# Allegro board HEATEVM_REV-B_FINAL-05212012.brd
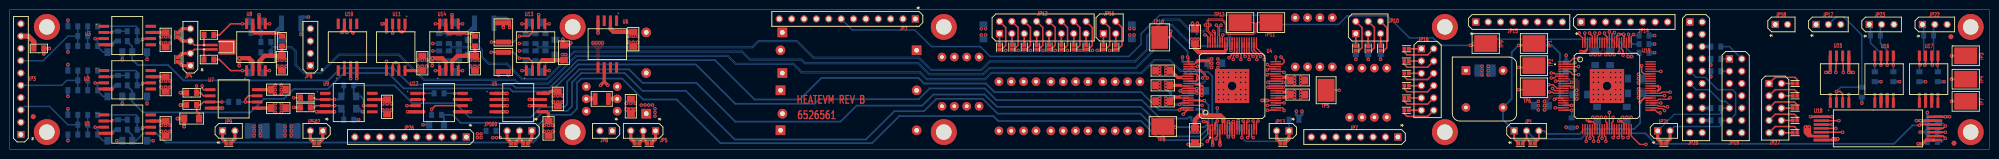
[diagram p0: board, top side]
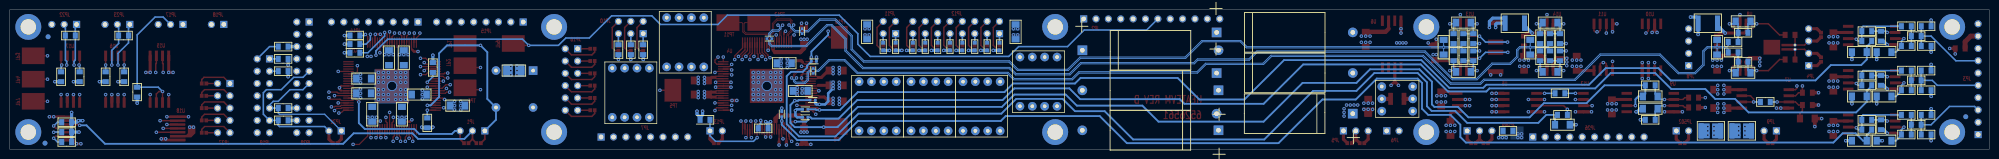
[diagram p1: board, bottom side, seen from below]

Outline 406.4 x 28.83 mm; copper layers: TOP, L2_GND, L3_PWR, L4_SIG, L5_SIG, L6_PWR, L7_GND, BOTTOM. Coordinates in mm from the lower left corner of the outline.
Outline path: 0,28.83 0,0 406.4,0 406.4,28.83 0,28.83

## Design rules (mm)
net group DP1: nets ADC_CH5M ADC_CH5P
net group DP2: nets ADC_CH7M ADC_CH7P
net group DP3: nets ADC_CH8M ADC_CH8P

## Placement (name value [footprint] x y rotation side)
C1  0.1u  [1206]  127.51 8.89 90 top
C2  68u 60V 200C  [CAP_AXL_641X312_1100]  158.62 24.13 180 bottom
C3  68u 60V 200C  [CAP_AXL_641X312_1100]  158.24 12.19 0 bottom
C4  68u 60V 200C  [CAP_AXL_641X312_1100]  158.62 15.75 180 bottom
C5  1u-DNI  [1210]  121.54 10.41 0 top
C7  68u 60V 200C  [CAP_AXL_641X312_1100]  186.18 20.45 180 bottom
C8  0.1u  [1206]  244.09 12.06 180 bottom
C9  0.1u  [1206]  112.52 10.41 270 top
C10  0.1u  [1206]  236.73 13.21 180 top
C11  10n  [1206]  90.17 16 0 bottom
C12  0.1u  [1206]  243.33 2.92 270 top
C13  0.1u  [1206]  243.33 23.24 90 top
C14  0.1u  [1206]  230.38 24.26 90 bottom
C15  68u 60V 200C  [CAP_AXL_641X312_1100]  158.24 3.94 0 bottom
C16  0.1u  [1206]  236.73 16.26 180 top
C17  0.033u  [0805]  17.02 7.11 0 bottom
C18  0.1u  [1206]  50.55 15.81 0 bottom
C20  0.1u  [1206]  50.55 26.42 0 bottom
C21  0.1u  [1206]  128.02 22.73 270 top
C22  0.1u  [1206]  37.34 6.35 180 top
C23  0.1u  [1206]  26.67 20.07 0 bottom
C24  0.033u  [0805]  17.02 16.26 0 bottom
C25  0.1u  [1206]  26.67 10.92 0 bottom
C26  0.1u  [1206]  32 22.61 270 top
C27  1u  [CAP_THVT_SMX3_300X250_100]  118.36 12.95 0 bottom
C28  0.1u  [1206]  325.88 7.24 90 bottom
C29  0.1u  [1206]  322.33 11.3 0 bottom
C30  0.1u  [1206]  21.59 20.07 0 bottom
C31  0.1u  [1206]  328.55 18.92 270 bottom
C32  0.033u  [0805]  17.02 25.4 0 bottom
C33  0.1u  [1206]  21.59 10.92 0 bottom
C34  0.1u  [1206]  236.73 9.91 180 top
C35  0.1u  [1206]  32 13.46 270 top
C37  0.1u  [1206]  21.59 1.78 0 bottom
C39  0.1u  [1206]  32 4.32 270 top
C40  0.1u  [1206]  26.67 1.78 0 bottom
C42  68u 60V 200C  [CAP_AXL_641X312_1100]  130.68 7.37 0 bottom
C43  0.1u  [1206]  264.41 14.22 0 top
C44  0.1u  [1206]  110.62 4.32 270 top
C45  10n  [1206]  69.6 10.92 0 bottom
C48  10n  [1206]  90.17 26.16 0 bottom
C50  0.1u  [1206]  69.6 8.38 0 bottom
C51  0.1u  [1206]  325.5 18.92 270 bottom
C52  0.1u  [1206]  314.45 9.02 180 bottom
C53  0.1u  [1206]  331.98 7.24 90 bottom
C54  0.1u  [1206]  87.63 5.08 180 bottom
C56  10n  [1206]  107.95 26.16 0 bottom
C57  10n  [1206]  112.01 21.08 270 bottom
C58  10n  [1206]  107.95 16 0 bottom
C62  SMX4-10u  [CAP_THVT_SMX4_440X400_100]  221.36 13.97 270 bottom
C500  0.1u  [1206]  55.12 12.32 0 top
C501  0.1u  [1206]  55.12 8.51 0 top
C502  0.1u  [1206]  55.88 17.78 270 top
C503  0.22u  [1812]  50.8 3.81 0 bottom
C504  10n  [1206]  55.88 21.08 270 bottom
C505  0.22u  [1812]  57.78 26.04 0 bottom
C506  0.22u  [1812]  101.35 18.03 270 top
C507  0.22u  [1812]  101.35 24.13 90 top
C508  0.1u  [1206]  113.79 19.94 90 top
C509  0.1u  [1206]  95.5 17.78 270 top
C510  0.1u  [1206]  77.47 8.76 270 top
C511  10n  [1206]  94.23 21.08 270 bottom
C512  0.1u  [1206]  84.71 17.78 90 top
C513  0.22u  [1812]  57.15 3.81 180 bottom
C514  0.1u  [1206]  264.41 11.3 0 top
C517  0.22u  [1812]  97.41 26.04 0 bottom
C518  0.1u  [1206]  247.4 17.78 0 bottom
C519  1n  [0402]  241.43 16.19 90 bottom
C520  1n  [0402]  243.71 24.38 90 bottom
C521  1n  [0402]  250.44 22.86 180 bottom
C522  100p  [0402]  247.9 7.24 90 bottom
C523  100p  [0402]  243.08 6.6 0 bottom
C524  100p  [0402]  243.08 8.26 0 bottom
C525  100p  [0402]  241.3 18.16 180 bottom
C526  100p  [0402]  241.55 10.16 180 bottom
C527  SMX4-10u  [CAP_THVT_SMX4_440X400_100]  199.01 19.05 270 bottom
C528  SMX4-10u  [CAP_THVT_SMX4_440X400_100]  210.69 13.97 270 bottom
C530  SMX4-10u  [CAP_THVT_SMX4_440X400_100]  232.03 13.97 270 bottom
C531  SMX4-10u  [CAP_THVT_SMX4_440X400_100]  263.91 17.02 90 bottom
C532  SMX4-10u  [CAP_THVT_SMX4_440X400_100]  275.08 6.6 90 bottom
C533  0.1u  [1206]  199.9 24.26 90 bottom
C534  0.1u  [1206]  302.89 16.26 180 bottom
C535  0.1u  [1206]  333.76 11.56 180 bottom
C536  0.1u  [1206]  333.76 14.61 180 bottom
JP1  FLASH_CLK  [HDR_THVT_1X3_100]  308.86 3.81 90 top
JP2  PWR_INPUT  [HDR_THVT_1X12_100]  185.93 26.92 270 top
JP3  AMP_INPUT_A  [HDR_THVT_1X10_100]  2.29 3.05 180 top
JP4  EXT_RTD  [HDR_THVT_1X4_100]  37.08 17.27 180 top
JP5  VREF_SEL  [HDR_THVT_1X3_100]  132.59 3.81 270 top
JP6  EXT_VREF  [HDR_THVT_1X2_100]  123.7 3.81 270 top
JP7  DOUT_TAP  [HDR_THVT_1X8_100]  284.99 2.54 270 top
JP8  CONN PCB 4  [HDR_THVT_1X4_100]  61.72 17.27 180 top
JP9  AMP5_VCOM_SEL  [HDR_THVT_1X2_100]  43.69 3.81 90 top
JP10  AD_FORMAT  [HDR_THVT_2X3_100_M]  276.35 23.88 90 top
JP11  AD_MODE  [HDR_THVT_2X2_100_M]  224.54 23.88 90 top
JP12  DISABLE_CHANNEL  [HDR_THVT_2X8_100_M]  203.2 23.88 90 top
JP13  DISABLE_CLKDIV  [HDR_THVT_1X2_100]  262.64 3.81 270 top
JP14  GPIO  [HDR_THVT_1X8_100]  322.58 26.29 90 top
JP15  HET_AND_GPIO  [HDR_THVT_1X8_100]  300.99 26.29 90 top
JP16  AD_CONTROL  [HDR_THVT_2X6_100_M]  289.81 20.76 0 top
JP17  RS485_CTRL  [HDR_THVT_1X3_100]  370.84 25.78 90 top
JP18  RS485_DATA  [HDR_THVT_1X2_100]  362.46 25.78 90 top
JP19  JTAG_7X2  [HDR_THVT_2X7_100_M]  353.06 18.67 0 top
JP20  JTAG_10X2  [HDR_THVT_2X10_100_M]  344.93 26.29 0 top
JP21  JTCLK_SEL  [HDR_THVT_1X2_100]  338.33 3.81 90 top
JP22  CAN1  [HDR_THVT_1X3_100]  392.68 25.78 90 top
JP23  CAN2  [HDR_THVT_1X3_100]  381.76 25.78 90 top
JP26  AMP_INPUTS_B  [HDR_THVT_1X10_100]  93.73 2.54 270 top
JP27  SPI2_M-IF_CNTRL  [HDR_THVT_2X5_100_M]  361.19 13.59 0 top
JP500  VCOM_SEL  [HDR_THVT_1X3_100]  107.19 3.81 270 top
JP502  AMP8_VCOM_SEL  [HDR_THVT_1X2_100]  64.26 3.81 270 top
MNT1  440_SCREW_MOUNT  [MFG_125_PTH]  7.62 3.56 0 top
MNT2  440_SCREW_MOUNT  [MFG_125_PTH]  7.62 25.27 0 top
MNT3  440_SCREW_MOUNT  [MFG_125_PTH]  115.57 3.56 0 top
MNT4  440_SCREW_MOUNT  [MFG_125_PTH]  115.57 25.27 0 top
MNT5  440_SCREW_MOUNT  [MFG_125_PTH]  294.64 3.56 0 top
MNT6  440_SCREW_MOUNT  [MFG_125_PTH]  294.64 25.27 0 top
MNT7  440_SCREW_MOUNT  [MFG_125_PTH]  402.59 3.56 0 top
MNT8  440_SCREW_MOUNT  [MFG_125_PTH]  402.59 25.27 0 top
MNT9  440_SCREW_MOUNT  [MFG_125_PTH]  191.77 25.27 0 top
MNT10  440_SCREW_MOUNT  [MFG_125_PTH]  191.77 3.56 0 top
NOREF  -  []  0 0 0 top
NOREF#2  -  []  0 0 90 top
NOREF#3  -  [unnamed#2]  4.83 6.73 0 top
NOREF#4  -  [unnamed#2]  399.16 1.27 0 top
NOREF#5  -  []  371.98 107.95 0 top
NOREF#6  -  [unnamed#2]  398.53 23.24 0 top
NOREF#7  -  []  146.56 13.46 0 top
NOREF#8  -  []  375.67 17.4 180 bottom
NOREF#9  -  [unnamed#2]  398.53 23.24 180 bottom
NOREF#10  -  [unnamed#2]  399.16 1.27 180 bottom
NOREF#11  -  [unnamed#2]  4.83 6.73 180 bottom
OSC1  FMI_7M500_OSC  [XTAL_4_THVT_505X505]  302.77 12.45 270 top
R1  10K  [0603]  205.74 21.21 90 bottom
R2  10K  [0603]  224.54 21.21 90 bottom
R3  10K  [0805]  281.43 20.57 90 bottom
R4  10K  [0805]  278.89 20.57 90 bottom
R5  10K  [0805]  276.35 20.57 90 bottom
R6  1.0K  [0805]  251.71 4.32 180 bottom
R7  10K  [0603]  227.08 21.21 90 bottom
R8  10K  [0603]  203.2 21.21 90 bottom
R9  10K  [0603]  208.28 21.21 90 bottom
R10  10K  [0603]  210.82 21.21 90 bottom
R11  10K  [0603]  213.36 21.21 90 bottom
R12  10K  [0603]  215.9 21.21 90 bottom
R13  80.6K  [0805]  14.99 5.08 0 bottom
R14  2.00K  [0805]  5.97 20.83 0 top
R15  49.9  [0805]  25.15 4.06 180 bottom
R16  20K-DNI  [0805]  12.95 7.11 180 bottom
R17  2.0K-DNI  [0805]  12.95 3.05 0 bottom
R18  22K  [0805]  40.89 23.62 180 top
R19  68K  [0805]  50.55 24.07 180 bottom
R20  68K  [0805]  50.55 18.1 180 bottom
R21  22K  [0805]  40.89 18.54 180 top
R24  1.0K  [0805]  37.34 11.68 0 top
R25  1.0K  [0805]  45.97 9.78 0 bottom
R26  220  [0805]  37.34 9.14 0 top
R27  20K-DNI  [0805]  12.95 16.26 180 bottom
R28  2.00K-DNI  [0805]  12.95 12.19 0 bottom
R29  80.6K  [0805]  14.99 14.22 0 bottom
R30  10K  [0805]  17.02 3.05 0 bottom
R31  49.9  [0805]  25.15 13.21 180 bottom
R32  20K-DNI  [0805]  12.95 25.4 180 bottom
R33  2.00K-DNI  [0805]  12.95 21.34 0 bottom
R34  80.6K  [0805]  14.99 23.37 0 bottom
R35  49.9  [0805]  25.15 22.35 180 bottom
R37  10K  [0805]  60.71 10.67 180 top
R38  10K  [0805]  69.6 13.21 0 bottom
R39  10K  [0805]  60.71 8.64 0 top
R40  10K  [0805]  69.6 6.1 0 bottom
R42  402  [0805]  88.14 11.56 0 bottom
R44  10K  [0805]  17.02 12.19 0 bottom
R45  200  [0805]  87.63 7.11 0 bottom
R46  10K  [0805]  17.02 21.34 0 bottom
R47  10K  [0805]  107.95 22.86 90 bottom
R48  10K  [0805]  105.92 22.86 270 bottom
R49  49.9  [0805]  109.98 22.86 90 bottom
R50  49.9  [0805]  109.98 19.3 270 bottom
R51  10K  [0805]  107.95 19.3 270 bottom
R52  10K  [0805]  105.92 19.3 90 bottom
R53  200  [0805]  88.14 22.86 270 bottom
R54  50K  [0805]  90.17 22.86 90 bottom
R55  200  [0805]  88.14 19.3 270 bottom
R56  50K  [0805]  90.17 19.3 270 bottom
R57  200  [0805]  92.2 22.86 90 bottom
R58  200  [0805]  92.2 19.3 270 bottom
R59  200  [0805]  98.81 3.81 0 bottom
R60  10K  [0603]  218.44 21.21 90 bottom
R61  10K  [0603]  220.98 21.21 90 bottom
R62  10K  [0805]  263.65 6.1 0 bottom
R63  10K  [0805]  392.05 14.99 90 bottom
R64  10K  [0805]  380.24 11.81 270 bottom
R65  10K  [0805]  350.27 5.97 0 bottom
R66  10K  [0805]  350.27 8.51 0 bottom
R67  10K  [0805]  350.27 18.67 180 bottom
R68  10K-DNI  [0805]  350.27 16.13 180 bottom
R69  10K  [0805]  350.27 21.21 0 bottom
R70  33K  [0805]  335.53 19.94 180 bottom
R71  33K  [0805]  319.53 16.89 90 bottom
R72  10K  [0805]  395.86 14.99 90 bottom
R73  10K  [0805]  382.9 14.99 90 bottom
R74  10K  [0805]  386.71 14.99 90 bottom
R78  120  [0805]  383.03 23.5 180 bottom
R79  120  [0805]  393.95 23.5 180 bottom
R81  33K  [0805]  394.72 3.56 180 bottom
R83  33K  [0805]  335.53 21.72 180 bottom
R84  33K  [0805]  335.53 23.5 180 bottom
R85  33K  [0805]  320.68 5.46 90 bottom
R92  10K  [0805]  25.15 6.1 0 bottom
R93  10K-DNI  [0805]  22.23 5.08 90 bottom
R94  10K  [0805]  25.15 15.24 0 bottom
R95  10K-DNI  [0805]  22.23 14.22 90 bottom
R96  10K-DNI  [0805]  22.23 23.37 90 bottom
R97  10K  [0805]  25.15 24.38 0 bottom
R98  33K  [0805]  394.72 5.59 180 bottom
R99  33K  [0805]  394.72 1.52 180 bottom
R500  10K  [0805]  55.88 22.35 90 top
R501  49.9  [0805]  52.58 20 180 bottom
R502  49.9  [0805]  52.58 22.16 180 bottom
R503  10K-DNI  [0805]  95.5 22.35 90 top
RTD  1.0K  [SENSOR_RTD_118X79_35]  43.69 21.08 180 top
SB1  SBridge  [SHORTING_BRIDGE]  34.54 23.62 90 top
SB2  SBridge  [SHORTING_BRIDGE]  34.54 18.54 270 top
SB3  SBridge  [SHORTING_BRIDGE]  131.32 1.27 0 top
SB4  SBridge  [SHORTING_BRIDGE]  128.78 1.27 180 top
SB5  SBridge  [SHORTING_BRIDGE]  44.96 1.27 180 top
SB6  SBridge  [SHORTING_BRIDGE]  62.99 1.27 0 top
SB7  SBridge  [SHORTING_BRIDGE]  105.92 1.27 180 top
SB8  SBridge  [SHORTING_BRIDGE]  103.38 1.27 0 top
SB9  SBridge  [SHORTING_BRIDGE]  203.2 21.08 90 top
SB10  SBridge  [SHORTING_BRIDGE]  205.74 21.08 90 top
SB11  SBridge  [SHORTING_BRIDGE]  208.28 21.08 90 top
SB12  SBridge  [SHORTING_BRIDGE]  210.82 21.08 90 top
SB13  SBridge  [SHORTING_BRIDGE]  213.36 21.08 90 top
SB14  SBridge  [SHORTING_BRIDGE]  215.9 21.08 90 top
SB15  SBridge  [SHORTING_BRIDGE]  218.44 21.08 90 top
SB16  SBridge  [SHORTING_BRIDGE]  220.98 21.08 90 top
SB17  SBridge  [SHORTING_BRIDGE]  276.35 20.83 90 top
SB18  SBridge  [SHORTING_BRIDGE]  278.89 20.83 90 top
SB19  SBridge  [SHORTING_BRIDGE]  281.43 20.83 90 top
SB20  SBridge  [SHORTING_BRIDGE]  224.54 21.08 90 top
SB21  SBridge  [SHORTING_BRIDGE]  261.37 1.27 0 top
SB22  SBridge  [SHORTING_BRIDGE]  227.08 21.08 90 top
SB23  SBridge  [SHORTING_BRIDGE]  312.67 1.27 0 top
SB24  SBridge  [SHORTING_BRIDGE]  310.13 1.27 180 top
SB25  SBridge  [SHORTING_BRIDGE]  339.6 1.27 180 top
SB26  SBridge  [SHORTING_BRIDGE]  366.52 13.59 180 top
SB27  SBridge  [SHORTING_BRIDGE]  366.52 11.05 180 top
SB28  SBridge  [SHORTING_BRIDGE]  366.52 8.51 180 top
SB29  SBridge  [SHORTING_BRIDGE]  366.52 5.97 180 top
SB30  SBridge  [SHORTING_BRIDGE]  366.52 3.43 180 top
SB31  SBridge  [SHORTING_BRIDGE]  286.77 15.68 0 top
SB32  SBridge  [SHORTING_BRIDGE]  286.77 18.22 0 top
SB33  SBridge  [SHORTING_BRIDGE]  286.77 20.76 0 top
SB34  SBridge  [SHORTING_BRIDGE]  286.77 13.14 0 top
SB35  SBridge  [SHORTING_BRIDGE]  286.77 10.6 0 top
SB36  SBridge  [SHORTING_BRIDGE]  286.77 8.06 0 top
TP1  MCU_RSTn  [TP_SMVT_112X150]  312.93 21.84 90 top
TP2  MCU_AWD  [TP_SMVT_112X150]  312.93 17.27 90 top
TP3  CAN1_LPBK  [TP_SMVT_112X150]  401.57 19.3 90 top
TP4  CAN2_LPBK  [TP_SMVT_112X150]  401.57 14.48 90 top
TP5  ADC_TEST  [TP_SMVT_112X150]  270.26 12.19 0 top
TP6  SCI1TX  [TP_SMVT_112X150]  312.93 12.7 270 top
TP7  FLSH_WPn  [TP_SMVT_112X150]  401.57 9.91 90 top
TP8  ADC_CH4  [TP_SMVT_112X150]  236.73 4.7 90 top
TP9  PORSTn  [TP_SMVT_112X150]  303.02 21.84 90 top
TP10  ADC_CH6  [TP_SMVT_112X150]  236.09 23.11 180 top
TP11  ADC_CH7p  [TP_SMVT_112X150]  258.95 26.16 270 top
TP12  ADC_CH7m  [TP_SMVT_112X150]  252.6 26.16 270 top
U1  OPA211SHKJ  [CDFF_8_289X232_50]  24.13 5.21 0 top
U2  OPA211SHKJ  [CDFF_8_289X232_50]  24.13 14.35 0 top
U3  OPA211SHKJ  [CDFF_8_289X232_50]  24.13 23.5 0 top
U4  ADS1278SHFQ  [CQFP_84_544X544_20]  250.95 13.08 90 top
U5  OPA2333SHKJ  [CDFF_8_289X232_50]  104.39 9.65 0 top
U6  REF5025SHKJ  [CDFF_8_289X232_50]  122.68 21.72 270 top
U7  OPA2333SHKJ  [CDFF_8_289X232_50]  45.97 10.41 0 top
U8  THS4521SHKJ  [CDFF_8_289X232_50]  50.55 21.08 90 top
U9  OPA211SHKJ  [CDFF_8_289X232_50]  69.6 9.65 0 top
U10  OPA211SHKJ  [CDFF_8_289X232_50]  69.34 21.08 90 top
U11  OPA2333SHKJ  [CDFF_8_289X232_50]  79.25 21.08 270 top
U12  INA333SHKJ  [CDFF_8_289X232_50]  88.14 9.65 0 top
U13  THS4521SHKJ  [CDFF_8_289X232_50]  107.95 21.08 90 top
U14  THS4521SHKJ  [CDFF_8_289X232_50]  90.17 21.08 90 top
U15  SN65HVD11SHKJ  [CDFF_8_289X232_50]  375.67 14.48 90 top
U16  SN65HVD233SHKJ  [CDFF_8_289X232_50]  384.81 14.48 90 top
U17  SN65HVD233SHKJ  [CDFF_8_289X232_50]  393.95 14.48 90 top
U18  SM28VLT32  [CDFP_14_290X708_31]  383.54 4.32 180 top
U19  SM470R1B1MHFQS  [CQFP_84_544X544_20]  327.91 13.08 0 top

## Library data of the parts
C1 C5 C8-C14 C16-C18 C20-C26 C28-C35 C37 C39 C40 C43-C45 C48 C50-C54 C56-C58 C500-C514 C517-C526 C533-C536 = CAP NP
C2-C4 C7 C15 C42 = HCB100680HT
C27 = CAP-STKD
C62 C527 C528 C530-C532 = CAP-STKD-4
JP1 JP5 JP17 JP22 JP23 JP500 = CONN PCB 3
JP2 = CONN PCB 12
JP3 JP26 = CONN PCB 10
JP4 JP8 = CONN PCB 4
JP6 JP9 JP13 JP18 JP21 JP502 = CONN PCB 2
JP7 JP14 JP15 = CONN PCB 8
JP10 = CONN PCB 3X2
JP11 = CONN PCB 2X2
JP12 = CONN PCB 8X2
JP16 = CONN PCB 6X2
JP19 = CONN PCB 7X2
JP20 = CONN PCB 10X2
JP27 = CONN PCB 5X2
MNT1-MNT10 = GND_HRDW_MOUNT
OSC1 = FMI_7M500_OSC
R1-R21 R24-R35 R37-R40 R42 R44-R74 R78 R79 R81 R83-R85 R92-R99 R500-R503 RTD = R
SB1-SB36 = SBridge
TP1-TP12 = SMT_TESTLOOP
U1-U3 U9 U10 = OPA211SHKJ
U4 = ADS1278SHFQ
U5 U7 U11 = OPA2333SHKJ
U6 = REF5025SHKJ
U8 U13 U14 = THS4521SHKJ
U12 = INA333SHKJ
U15 = SN65HVD11SHKJ
U16 U17 = SN65HVD233SHKJ
U18 = SM28VLT32
U19 = SM470R1B1MHFQS

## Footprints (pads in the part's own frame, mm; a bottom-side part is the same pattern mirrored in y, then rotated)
0402
  rect 0.508x0.508 smd: 1(-0.521,0) 2(0.521,0)
0603
  rect 0.762x0.813 smd: 1(-0.787,0) 2(0.787,0)
0805
  rect 1.016x1.27 smd: 1(-1.016,0) 2(1.016,0)
1206
  rect 1.27x1.6 smd: 1(-1.524,0) 2(1.524,0)
1210
  rect 0.965x2.489 smd: 1(-1.372,0) 2(1.372,0)
1812
  rect 1.016x3.175 smd: 1(-1.994,0) 2(1.994,0)
CAP_AXL_641X312_1100
  rect 1.981x1.981 hole 0.965: 1(0,0)
  round 1.981 hole 0.965: 2(27.953,0.013)
CAP_THVT_SMX3_300X250_100
  round 1.778 hole 0.762: 1(0,0) 2(0,2.54) 3(0,5.08) 4(6.35,0) 5(6.35,2.54) 6(6.35,5.08)
CAP_THVT_SMX4_440X400_100
  round 1.778 hole 0.762: 1(0,0) 2(0,2.54) 3(0,5.08) 4(0,7.62) 5(10.16,0) 6(10.16,2.54) 7(10.16,5.08) 8(10.16,7.62)
CDFF_8_289X232_50
  rect 2.159x0.61 smd: 1(-4.828,1.905) 2(-4.828,0.635) 3(-4.828,-0.635) 4(-4.828,-1.905) 5(4.828,-1.905) 6(4.828,-0.635) 7(4.828,0.635) 8(4.828,1.905)
CDFP_14_290X708_31
  rect 3.175x0.508 smd: 1(-11.608,2.4) 2(-11.608,1.6) 3(-11.608,0.8) 4(-11.608,0) 5(-11.608,-0.8) 6(-11.608,-1.6) 7(-11.608,-2.4) 8(11.608,-2.4) 9(11.608,-1.6) 10(11.608,-0.8) 11(11.608,0) 12(11.608,0.8) 13(11.608,1.6) 14(11.608,2.4)
CQFP_84_544X544_20
  rect 2.159x0.254 smd: 1(-8.954,5) 2(-8.954,4.5) 3(-8.954,4) 4(-8.954,3.5) 5(-8.954,3) 6(-8.954,2.5) 7(-8.954,2) 8(-8.954,1.5) 9(-8.954,1) 10(-8.954,0.5) 11(-8.954,0) 12(-8.954,-0.5) 13(-8.954,-1) 14(-8.954,-1.5) 15(-8.954,-2) 16(-8.954,-2.5) 17(-8.954,-3) 18(-8.954,-3.5) 19(-8.954,-4) 20(-8.954,-4.5) 21(-8.954,-5) 43(8.954,-5) 44(8.954,-4.5) 45(8.954,-4) 46(8.954,-3.5) 47(8.954,-3) 48(8.954,-2.5) 49(8.954,-2) 50(8.954,-1.5) 51(8.954,-1) 52(8.954,-0.5) 53(8.954,0) 54(8.954,0.5) 55(8.954,1) 56(8.954,1.5) 57(8.954,2) 58(8.954,2.5) 59(8.954,3) 60(8.954,3.5) 61(8.954,4) 62(8.954,4.5) 63(8.954,5)
  rect 0.254x2.159 smd: 22(-5,-8.954) 23(-4.5,-8.954) 24(-4,-8.954) 25(-3.5,-8.954) 26(-3,-8.954) 27(-2.5,-8.954) 28(-2,-8.954) 29(-1.5,-8.954) 30(-1,-8.954) 31(-0.5,-8.954) 32(0,-8.954) 33(0.5,-8.954) 34(1,-8.954) 35(1.5,-8.954) 36(2,-8.954) 37(2.5,-8.954) 38(3,-8.954) 39(3.5,-8.954) 40(4,-8.954) 41(4.5,-8.954) 42(5,-8.954) 64(5,8.954) 65(4.5,8.954) 66(4,8.954) 67(3.5,8.954) 68(3,8.954) 69(2.5,8.954) 70(2,8.954) 71(1.5,8.954) 72(1,8.954) 73(0.5,8.954) 74(0,8.954) 75(-0.5,8.954) 76(-1,8.954) 77(-1.5,8.954) 78(-2,8.954) 79(-2.5,8.954) 80(-3,8.954) 81(-3.5,8.954) 82(-4,8.954) 83(-4.5,8.954) 84(-5,8.954)
  rect 7.036x7.036 smd: 85(0,0)
HDR_THVT_1X2_100
  rect 1.473x1.473 hole 0.965: 1(0,0)
  round 1.473 hole 0.965: 2(0,-2.54)
HDR_THVT_1X3_100
  rect 1.473x1.473 hole 0.965: 1(0,0)
  round 1.473 hole 0.965: 2(0,-2.54) 3(0,-5.08)
HDR_THVT_1X4_100
  rect 1.473x1.473 hole 0.965: 1(0,0)
  round 1.473 hole 0.965: 2(0,-2.54) 3(0,-5.08) 4(0,-7.62)
HDR_THVT_1X8_100
  rect 1.473x1.473 hole 0.965: 1(0,0)
  round 1.473 hole 0.965: 2(0,-2.54) 3(0,-5.08) 4(0,-7.62) 5(0,-10.16) 6(0,-12.7) 7(0,-15.24) 8(0,-17.78)
HDR_THVT_1X10_100
  rect 1.473x1.473 hole 0.965: 1(0,0)
  round 1.473 hole 0.965: 2(0,-2.54) 3(0,-5.08) 4(0,-7.62) 5(0,-10.16) 6(0,-12.7) 7(0,-15.24) 8(0,-17.78) 9(0,-20.32) 10(0,-22.86)
HDR_THVT_1X12_100
  rect 1.473x1.473 hole 0.965: 1(0,0)
  round 1.473 hole 0.965: 2(0,-2.54) 3(0,-5.08) 4(0,-7.62) 5(0,-10.16) 6(0,-12.7) 7(0,-15.24) 8(0,-17.78) 9(0,-20.32) 10(0,-22.86) 11(0,-25.4) 12(0,-27.94)
HDR_THVT_2X2_100_M
  rect 1.473x1.473 hole 0.965: 1(0,0)
  round 1.473 hole 0.965: 2(2.54,0) 3(0,-2.54) 4(2.54,-2.54)
HDR_THVT_2X3_100_M
  rect 1.473x1.473 hole 0.965: 1(0,0)
  round 1.473 hole 0.965: 2(2.54,0) 3(0,-2.54) 4(2.54,-2.54) 5(0,-5.08) 6(2.54,-5.08)
HDR_THVT_2X5_100_M
  rect 1.473x1.473 hole 0.965: 1(0,0)
  round 1.473 hole 0.965: 2(2.54,0) 3(0,-2.54) 4(2.54,-2.54) 5(0,-5.08) 6(2.54,-5.08) 7(0,-7.62) 8(2.54,-7.62) 9(0,-10.16) 10(2.54,-10.16)
HDR_THVT_2X6_100_M
  rect 1.473x1.473 hole 0.965: 1(0,0)
  round 1.473 hole 0.965: 2(2.54,0) 3(0,-2.54) 4(2.54,-2.54) 5(0,-5.08) 6(2.54,-5.08) 7(0,-7.62) 8(2.54,-7.62) 9(0,-10.16) 10(2.54,-10.16) 11(0,-12.7) 12(2.54,-12.7)
HDR_THVT_2X7_100_M
  rect 1.473x1.473 hole 0.965: 1(0,0)
  round 1.473 hole 0.965: 2(2.54,0) 3(0,-2.54) 4(2.54,-2.54) 5(0,-5.08) 6(2.54,-5.08) 7(0,-7.62) 8(2.54,-7.62) 9(0,-10.16) 10(2.54,-10.16) 11(0,-12.7) 12(2.54,-12.7) 13(0,-15.24) 14(2.54,-15.24)
HDR_THVT_2X8_100_M
  rect 1.473x1.473 hole 0.965: 1(0,0)
  round 1.473 hole 0.965: 2(2.54,0) 3(0,-2.54) 4(2.54,-2.54) 5(0,-5.08) 6(2.54,-5.08) 7(0,-7.62) 8(2.54,-7.62) 9(0,-10.16) 10(2.54,-10.16) 11(0,-12.7) 12(2.54,-12.7) 13(0,-15.24) 14(2.54,-15.24) 15(0,-17.78) 16(2.54,-17.78)
HDR_THVT_2X10_100_M
  rect 1.473x1.473 hole 0.965: 1(0,0)
  round 1.473 hole 0.965: 2(2.54,0) 3(0,-2.54) 4(2.54,-2.54) 5(0,-5.08) 6(2.54,-5.08) 7(0,-7.62) 8(2.54,-7.62) 9(0,-10.16) 10(2.54,-10.16) 11(0,-12.7) 12(2.54,-12.7) 13(0,-15.24) 14(2.54,-15.24) 15(0,-17.78) 16(2.54,-17.78) 17(0,-20.32) 18(2.54,-20.32) 19(0,-22.86) 20(2.54,-22.86)
MFG_125_PTH
  round 5.334 hole 3.175: 1(0,0)
SENSOR_RTD_118X79_35
  rect 3.048x0.508 hole 0.356: 1(3.81,0.445) 2(3.81,-0.445)
SHORTING_BRIDGE
  rect 0.762x0.813 smd: 1(-0.457,0) 2(0.457,0)
TP_SMVT_112X150
  rect 3.429x4.699 smd: 1(0,0)
unnamed#2
  round 1.016 smd: (0,0)
XTAL_4_THVT_505X505
  rect 1.778x1.778 hole 0.762: 1(-3.81,-3.81)
  round 1.778 hole 0.762: 4(3.81,-3.81) 5(3.81,3.81) 8(-3.81,3.81)

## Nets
D7VCOM_P03: C506.1 JP26.3 U13.2(VCOM)
GND: C1.2 C2.2 C3.2 C4.2 C5.2 C7.2 C8.2 C9.2 C10.2 C12.2 C13.2 C14.2 C15.2 C16.2 C21.2 C22.2 C23.2 C25.2 C26.2 C27.4 C27.5 C27.6 C28.2 C29.2 C30.2 C31.2 C33.2 C34.2 C35.2 C37.2 C39.2 C40.2 C42.2 C43.2 C44.2 C50.2 C51.2 C52.2 C53.2 C54.2 C62.5 C62.6 C62.7 C62.8 C500.2 C501.2 C502.2 C503.2 C505.2 C506.2 C507.2 C508.2 C509.2 C510.2 C512.2 C513.2 C514.2 C517.2 C518.2 C525.2 C527.5 C527.6 C527.7 C527.8 C528.5 C528.6 C528.7 C528.8 C530.5 C530.6 C530.7 C530.8 C531.5 C531.6 C531.7 C531.8 C532.5 C532.6 C532.7 C532.8 C533.2 C534.2 C535.2 C536.2 JP2.2 JP2.4 JP2.6 JP2.9 JP2.12 JP3.1 JP3.4 JP3.6 JP3.8 JP3.10 JP6.2 JP8.1 JP11.2 JP11.4 JP12.2 JP12.4 JP12.6 JP12.8 JP12.10 JP12.12 JP12.14 JP12.16 JP13.2 JP17.1 JP19.4 JP19.10 JP19.12 JP20.4 JP20.6 JP20.8 JP20.10 JP20.12 JP20.14 JP20.16 JP20.18 JP20.20 JP22.3 JP23.3 JP26.8 JP27.4 MNT1.1(TP) MNT2.1(TP) MNT3.1(TP) MNT4.1(TP) MNT5.1(TP) MNT6.1(TP) MNT7.1(TP) MNT8.1(TP) MNT9.1(TP) MNT10.1(TP) OSC1.4(GND) R3.1 R4.1 R5.1 R6.2 R17.1 R24.1 R26.1 R28.1 R33.1 R40.2 R63.1 R65.1 R66.1 R69.1 R70.1 R72.1 R73.1 R74.1 R83.1 R85.1 R93.1 R95.1 R96.1 SB9.1 SB10.1 SB11.1 SB12.1 SB13.1 SB14.1 SB15.1 SB16.1 SB20.1 SB21.1 SB22.1 SB27.2 U1.4(VSRCM) U2.4(VSRCM) U3.4(VSRCM) U4.3(AGND1) U4.6(AGND2) U4.9(AGND3) U4.10(AGND4) U4.11(AGND5) U4.12(DGND1) U4.26(DGND2) U4.31(DGND3) U4.32(DGND4) U4.33(DGND5) U4.34(DGND6) U4.53(AGND6) U4.54(AGND7) U4.57(AGND8) U4.60(AGND9) U4.63(AGND10) U4.66(AGND11) U4.69(AGND12) U4.72(AGND13) U4.75(VREFM) U4.76(AGND14) U4.77(AGND15) U4.82(AGND16) U4.85(TGND) U5.4(VSRCM) U6.4(GND) U7.4(VSRCM) U8.6(VSRCM) U9.4(VSRCM) U10.4(VSRCM) U11.4(VSRCM) U12.4(VSRCM) U13.6(VSRCM) U14.6(VSRCM) U15.5(GND) U16.2(GND) U17.2(GND) U18.1(VSS1) U18.8(VSS2) U19.9(GND_CORE1) U19.16(VDIO_GND_1) U19.20(GND_CORE2) U19.27(GND_CORE3) U19.39(VDIO_GND_2) U19.51(VDIO_GND_3) U19.53(GND_CORE4) U19.67(ADC_GND) U19.70(GND_CORE5) U19.74(GND_CORE6) U19.82(VDIO_GND_4) U19.85(TGND)
0G_REF_VSRC: C44.1 JP3.9 R14.1 U5.5(INP_B)
0G_VREF_P04: C522.2 C523.2 C524.2 U4.2(ADINM_2) U4.5(ADINM_1) U4.84(ADINM_3) U5.6(INM_B) U5.7(OUT_B)
1P8VSRC: C3.1 C28.1 C29.1 C31.1 C536.1 JP2.8 U18.7(VCORE1) U18.14(VCORE2) U19.8(1P8VCORE_1) U19.17(1P8VCORE_2) U19.28(1P8VCORE_3) U19.54(1P8VCORE_4) U19.71(1P8VCORE_5) U19.75(1P8VCORE_6)
3P3VSRC: C2.1 C51.1 C52.1 C53.1 C534.1 C535.1 JP2.5 JP19.5 JP20.1 JP20.2 OSC1.8(VDD) R64.2 R67.2 R68.2 R71.2 R81.2 R84.1 R98.2 R99.2 U15.8(VCC) U16.3(VCC) U17.3(VCC) U18.6(VIO1) U18.13(VIO2) U19.15(3P3VDIO_1) U19.40(3P3VDIO_2) U19.52(3P3VDIO_3) U19.66(ADC_3P3VDD) U19.76(3P3VCCP) U19.81(3P3VDIO_4)
5P0VSRC: C4.1 C9.1 C12.1 C13.1 C16.1 C21.1 C26.1 C34.1 C35.1 C39.1 C500.1 C510.1 C512.1 C527.1 C527.2 C527.3 C527.4 C528.1 C528.2 C528.3 C528.4 C530.1 C530.2 C530.3 C530.4 JP2.11 JP3.2 U1.7(VSRCP) U2.7(VSRCP) U3.7(VSRCP) U4.7(AVDD1) U4.8(AVDD2) U4.55(AVDD3) U4.56(AVDD4) U4.70(AVDD5) U4.71(AVDD6) U4.78(AVDD7) U4.79(AVDD8) U5.8(VSRCP) U6.2(VIN) U7.8(VSRCP) U9.7(VSRCP) U10.7(VSRCP) U11.8(VSRCP) U12.7(VSRCP)
8PDN_P03: C517.1 R503.2 U14.7(PDN)
AD_1P8VSRC: C15.1 C43.1 C531.1 C531.2 C531.3 C531.4 JP2.3 U4.35(DVDD1) U4.36(DVDD2)
AD_3P3VSRC: C7.1 C14.1 C502.1 C508.1 C509.1 C514.1 C532.1 C532.2 C532.3 C532.4 C533.1 JP2.1 JP10.2 JP10.4 JP10.6 R1.1 R2.1 R7.1 R8.1 R9.1 R10.1 R11.1 R12.1 R60.1 R61.1 R62.2 R500.1 R503.1 SB17.1 SB18.1 SB19.1 U4.27(IOVDD1) U4.28(IOVDD2) U4.29(IOVDD3) U4.30(IOVDD4) U8.3(VSRCP) U13.3(VSRCP) U14.3(VSRCP)
AD_VCOM: JP500.1 SB7.1 U5.1(OUT_A) U5.2(INM_A)
ADC_CH1: C40.1 C522.1 R15.2 U4.4(ADINP_1)
ADC_CH2: C25.1 C523.1 R31.2 U4.1(ADINP_2)
ADC_CH3: C23.1 C524.1 R35.2 U4.83(ADINP_3)
ADC_CH4: C45.2 C526.1 R38.2 TP8.1(TP) U4.80(ADINP_4) U9.6(OUT)
ADC_CH5M: C504.1 C519.2 R502.1 U4.68(ADINM_5)
ADC_CH5P: C504.2 C519.1 R501.1 U4.67(ADINP_5)
ADC_CH6: C54.1 C525.1 R45.2 TP10.1(TP) U4.64(ADINP_6)
ADC_CH7M: C57.1 C520.2 R47.1 R49.1 TP12.1(TP) U4.62(ADINM_7)
ADC_CH7P: C57.2 C520.1 R50.1 R51.1 TP11.1(TP) U4.61(ADINP_7)
ADC_CH8M: C511.1 C521.2 R54.1 R57.1 U4.59(ADINM_8)
ADC_CH8P: C511.2 C521.1 R56.1 R58.1 U4.58(ADINP_8)
ADC_EVENT_P05: R73.2 U16.8(RS) U19.59(ADC_EVT)
ADCLK: JP16.11 SB36.2 U4.37(CLK)
ADSCLK: JP16.5 SB31.2 U4.38(SCLK)
ADSYNC: JP16.1 SB33.2 U4.39(FSYNC/DRDYN)
AMP_OUT_CH1_P02: C17.2 R15.1 R92.2 U1.6(OUT)
AMP_OUT_CH2_P02: C24.2 R31.1 R94.2 U2.6(OUT)
AMP_OUT_CH3_P02: C32.2 R35.1 R97.2 U3.6(OUT)
AMP_VCOM_CH5_P02: JP9.1 SB5.2 U8.2(VCOM)
AMP_VCOM_CH8_P03: JP502.1 SB6.2 U14.2(VCOM)
AWD_P05: R85.2 TP2.1(TP) U19.21(AWD)
BRDGM_P03: JP8.2 U11.5(INP_B)
BRDGP_P03: JP8.3 U11.3(INP_A)
BUF-BRDGM_P03: R55.1 U11.6(INM_B) U11.7(OUT_B)
BUF-BRDGP_P03: R53.2 U11.1(OUT_A) U11.2(INM_A)
CANH1_P05: JP22.1 R79.2 U17.7(CANH)
CANH2_P05: JP23.1 R78.2 U16.7(CANH)
CANL1_P05: JP22.2 R79.1 U17.6(CANL)
CANL2_P05: JP23.2 R78.1 U16.6(CANL)
CANRX_1_P05: U17.4(R) U19.49(HECANRX_1)
CANRX_2_P05: U16.4(R) U19.29(HECANRX_2)
CANTX_1_P05: U17.1(D) U19.50(HECANTX_1)
CANTX_2_P05: U16.1(D) U19.30(HECANTX_2)
CLKDIV_P04: JP13.1 R62.1 SB21.2 U4.15(CLKDIV)
CLKOUT_P05: JP1.3 SB23.2 U19.48(CLKOUT)
D6M_P03: JP26.5 U12.2(INM)
D6P_P03: JP26.6 U12.3(INP)
D7M_P03: JP26.1 R52.2
D7P_P03: JP26.2 R48.2
D7PDN_P03: C507.1 JP26.4 U13.7(PDN)
D485_A_P05: JP18.2 U15.6(DIF_A)
D485_B_P05: JP18.1 U15.7(DIF_AN)
D-BRDGM_P03: C11.1 R55.2 R56.2 U14.1(INM)
D-BRDGP_P03: C48.1 R53.1 R54.2 U14.8(INP)
D-RTDM_P02: C18.1 R20.2 R21.1 U8.1(INM)
D-RTDP_P02: C20.1 R18.1 R19.2 U8.8(INP)
DIN: JP16.7 SB34.2 U4.17(DIN)
DOUT1: JP7.1 JP16.9 SB35.2 U4.25(DOUT1)
DOUT2_P04: JP7.2 U4.24(DOUT2)
DOUT3_P04: JP7.3 U4.23(DOUT3)
DOUT4_P04: JP7.4 U4.22(DOUT4)
DOUT5_P04: JP7.5 U4.21(DOUT5)
DOUT6_P04: JP7.6 U4.20(DOUT6)
DOUT7_P04: JP7.7 U4.19(DOUT7)
DOUT8_P04: JP7.8 U4.18(DOUT8)
FLCLK_P05: JP1.2 SB23.1 SB24.1 U18.5(FLCLK)
FORMAT0_P04: JP10.1 R5.2 SB17.2 U4.42(FORMAT0)
FORMAT1_P04: JP10.3 R4.2 SB18.2 U4.41(FORMAT1)
FORMAT2_P04: JP10.5 R3.2 SB19.2 U4.40(FORMAT2)
GPIOA0_P05: JP14.1 U19.83(GPIOA/INT_0)
GPIOA1_P05: JP14.2 JP16.12 SB36.1 U19.80(GPIOA/INT_1)
GPIOA2_P05: JP14.3 U19.79(GPIOA/INT_2)
GPIOA3_P05: JP14.4 U19.78(GPIOA/INT_3)
GPIOA4_P05: JP14.5 U19.73(GPIOA/INT_4)
GPIOA5_P05: JP14.6 U19.58(GPIOA/INT_5)
GPIOA6_P05: JP14.7 U19.46(GPIOA/INT_6)
GPIOA7_P05: JP14.8 U19.47(GPIOA/INT_7)
HET2_P05: JP15.3 U19.41(HET2)
HET3_P05: JP15.2 U19.38(HET3)
HET4_P05: JP15.1 U19.37(HET4)
HET6_P05: JP15.8 U19.6(HET6)
HET8_P05: JP15.7 U19.7(HET8)
HOLDN_P05: R99.1 U18.2(HOLDN)
I-ADC_CH5M_P02: C18.2 R20.1 R501.2 U8.4(OUTP)
I-ADC_CH5P_P02: C20.2 R19.1 R502.2 U8.5(OUTM)
I-ADC_CH7M_P03: C56.2 R49.2 U13.5(OUTM)
I-ADC_CH7P_P03: C58.2 R50.2 U13.4(OUTP)
I-ADC_CH8M_P03: C11.2 R58.2 U14.4(OUTP)
I-ADC_CH8P_P03: C48.2 R57.2 U14.5(OUTM)
I_INM_4_P03: JP26.7 R37.2
I_INP_1_P02: C17.1 R13.2 R30.1
I_INP_2_P02: C24.1 R29.2 R44.1
I_INP_3_P02: C32.1 R34.2 R46.1
INM_1_P02: R92.1 R93.2 U1.2(INM)
INM_2_P02: R94.1 R95.2 U2.2(INM)
INM_3_P02: R96.2 R97.1 U3.2(INM)
INM_4_P03: C45.1 R37.1 R38.1 U9.2(INM)
INM_7_P03: C58.1 R51.2 R52.1 U13.1(INM)
INP_1_P02: C37.1 R30.2 U1.3(INP)
INP_2_P02: C33.1 R44.2 U2.3(INP)
INP_3_P02: C30.1 R46.2 U3.3(INP)
INP_4_P03: C50.1 R39.2 R40.1 U9.3(INP)
INP_7_P03: C56.1 R47.2 R48.1 U13.8(INP)
INT_2P5VREF_P02: JP5.1 SB3.2 U6.6(VOUT)
IO_CTRL_P05: JP17.2 R64.1 U15.2(REN) U15.3(DE)
ISO_VREF_P02: R25.2 U7.6(INM_B) U7.7(OUT_B)
JTCK_P05: JP19.11 JP20.9 JP21.2 R65.2 SB25.1 U19.45(JTCK)
JTDI_P05: JP19.3 JP20.5 R68.1 U19.43(JTDI)
JTDO_P05: JP19.7 JP20.13 U19.44(JTDO)
JTMS2_P05: R71.1 U19.10(JTMS2)
JTMS_P05: JP19.1 JP20.7 R67.1 U19.11(JTMS)
JTRSTN_P05: JP19.2 JP20.3 R69.2 U19.84(JTRSTN)
LBK1_P05: R72.2 TP3.1(TP) U17.5(LBK)
LBK2_P05: R74.2 TP4.1(TP) U16.5(LBK)
MCS_P05: JP27.2 SB26.2 U18.12(CSN)
MODE0_P04: JP11.1 R2.2 SB20.2 U4.44(MODE0)
MODE1_P04: JP11.3 R7.2 SB22.2 U4.43(MODE1)
MSCLK_P05: JP27.10 SB30.2 U18.9(SCK)
MSI_P05: JP27.6 SB28.2 U18.10(SI)
MSO_P05: JP27.8 SB29.2 U18.11(SO)
N66709_P04: C8.1 U4.73(VCOM) U5.3(INP_A)
N82092_P04: R6.1 TP5.1(TP) U4.13(TEST0) U4.14(TEST1)
OSCCLK_P05: JP1.1 OSC1.5(OUT) SB24.2 TP1.1(TP) U19.19(OSCIN)
OUT_CH6_P03: R45.1 U12.6(OUT)
OUTB_FB_P02: C22.1 R25.1 R26.2 U7.3(INP_A)
PDN_P02: C505.1 R500.2 U8.7(PDN)
PORSTN: JP2.7 TP9.1(TP) U19.68(PORSTN)
PWRDNN_1_P04: JP12.1 R8.2 SB9.2 U4.52(PWRDNN_1)
PWRDNN_2_P04: JP12.3 R1.2 SB10.2 U4.51(PWRDNN_2)
PWRDNN_3_P04: JP12.5 R9.2 SB11.2 U4.50(PWRDNN_3)
PWRDNN_4_P04: JP12.7 R10.2 SB12.2 U4.49(PWRDNN_4)
PWRDNN_5_P04: JP12.9 R11.2 SB13.2 U4.48(PWRDNN_5)
PWRDNN_6_P04: JP12.11 R12.2 SB14.2 U4.47(PWRDNN_6)
PWRDNN_7_P04: JP12.13 R60.2 SB15.2 U4.46(PWRDNN_7)
PWRDNN_8_P04: JP12.15 R61.2 SB16.2 U4.45(PWRDNN_8)
REFHI_P05: R84.2 U19.64(ADC_3P3V_REFHI)
REFLO_P05: R83.2 U19.65(ADC_GND_REFLO)
RJTCK_P05: JP19.9 JP20.11 JP21.1 R66.2 SB25.2
RSTN_P05: JP20.15 R81.1 U18.3(RSTN) U19.69(RSTN)
RTDM_P02: JP4.1 R24.2 SB2.2 U7.2(INM_A)
RTDP_P02: JP4.4 SB1.2 U7.1(OUT_A)
S-RTDM_P02: JP4.2 R21.2 RTD.1 SB2.1
S-RTDP_P02: JP4.3 R18.2 RTD.2 SB1.1
SCICLK3_P05: JP15.4 U19.14(SCICLK_3)
SCICLK_1_P05: JP17.3 U19.26(SCICLK_1)
SCIRX3_P05: JP15.5 U19.13(SCIRX__3)
SCIRX_1_P05: U15.1(R) U19.25(SCIRX__1)
SCITX3_P05: JP15.6 U19.12(SCITX_3)
SCITX_1_P05: TP6.1(TP) U15.4(D) U19.24(SCITX_1)
SPI2_CLK_P05: JP27.9 SB30.1 U19.31(SPI_CLK2)
SPI2_ENAN_P05: JP27.3 SB27.1 U19.34(SPI_ENAN2)
SPI2_MISO_P05: JP27.7 SB29.1 U19.32(SPI_MISO2)
SPI2_MOSI_P05: JP27.5 SB28.1 U19.33(SPI_MOSI2)
SPI2_SCSN_P05: JP27.1 SB26.1 U19.35(SPI_SCSN2)
SPI_CLK1_P05: JP16.6 SB31.1 U19.3(SPI_CLK1)
SPI_ENAN1_P05: JP16.4 SB32.1 U19.2(SPI_ENAN1)
SPI_MISO1_P05: JP16.10 SB35.1 U19.5(SPI_MISO1)
SPI_MOSI1_P05: JP16.8 SB34.1 U19.4(SPI_MOSI1)
SPI_SCSN1_P05: JP16.2 SB33.1 U19.1(SPI_SCSN1)
SRC_EXT_VCOM_P03: JP26.9 JP26.10 R59.1
STAT3_P05: R63.2 U17.8(RS) U19.42(HET0)
SYNCN: JP16.3 SB32.2 U4.16(SYNCN)
TEST_P05: R70.2 U19.72(TEST)
TRIMER_P02: C5.1 C27.1 C27.2 C27.3 U6.5(TRIM/NR)
U12_RG1_P03: R42.1 U12.1(RG1)
U12_RG2_P03: R42.2 U12.8(RG2)
VBRDGP_P03: JP8.4 U10.2(INM) U10.6(OUT)
VCOM: C503.1 C513.1 JP9.2 JP500.2 JP502.2 R59.2 SB5.1 SB6.1 SB7.2 SB8.2
VREF: C1.1 C10.1 C42.1 C62.1 C62.2 C62.3 C62.4 C501.1 C518.1 C526.2 JP5.2 JP500.3 R14.2 R16.2 R27.2 R32.2 R39.1 SB3.1 SB4.1 SB8.1 U4.65(ADINM_6) U4.74(VREFP) U4.81(ADINM_4) U7.5(INP_B) U10.3(INP) U12.5(REF)
WPN_P05: R98.1 TP7.1(TP) U18.4(WPN)
X-AXIS_P02: JP3.3 R13.1 R16.1 R17.2
XT_VOUT_P02: JP5.3 JP6.1 SB4.2
Y-AXIS_P02: JP3.5 R27.1 R28.2 R29.1
Z-AXIS_P02: JP3.7 R32.1 R33.2 R34.1

Pads without a net: JP2 10; JP19 6 8 13 14; JP20 17 19; OSC1 1; U1 1 5 8; U2 1 5 8; U3 1 5 8; U6 1 3 7 8; U9 1 5 8; U10 1 5 8; U19 18 22 23 36 55 56 57 60 61 62 63 77

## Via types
v1: diameter 0.711, hole 0.356, TOP to BOTTOM, 604 vias
v2: diameter 2.159, hole 1.778, TOP to BOTTOM, 2 vias

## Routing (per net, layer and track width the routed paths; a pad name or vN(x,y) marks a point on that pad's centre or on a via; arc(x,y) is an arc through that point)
D7VCOM_P03: length 37.6
  TOP w0.305: U13.2 107.31,18.03 106.55,18.8 v1(104.65,18.8) ; C506.1 v1(98.84,20.03)
  L4_SIG w0.305: v1(98.84,20.03) 94.83,20.03 89.79,14.99 89.79,5.71 88.65,4.57 JP26.3
  BOTTOM w0.305: v1(98.84,20.03) 103.42,20.03 v1(104.65,18.8)
GND: length 291.7
  TOP w0.254: U19.16 317.54,10.58 317.37,10.41 ; 338.45,12.19 338.34,12.08 U19.51 ; v1(243.71,11.62) 243.67,11.58 U4.77 240.78,11.58 v1(240.28,12.08) ; U4.66 243.65,17.08 243.71,17.14 v1(243.84,17.14) ; U19.70 329.91,23.34 330.07,23.49 ; U4.6 248.45,2.2 ; v1(240.28,12.08) U4.76 243.71,12.08 ; v1(240.28,12.08) 240.78,12.58 U4.75 243.64,12.58 v1(243.71,12.51) ; U4.26 v1(258.11,10.08) ; 324.61,5.71 324.99,5.71 325.41,5.29 U19.27 ; U19.20 v1(317.3,8.58) ; 338.33,13.08 U19.53 ; U4.82 v1(244.79,9.08) ; U4.69 243.6,15.58 ; U19.82 323.91,20.7 323.76,20.54 ; U4.57 248.95,23.53 v1(249.05,23.62) ; v1(327.41,24) 327.41,23.75 327.91,23.24 U19.74 ; v1(245.36,23.62) 245.62,23.62 245.95,23.29 U4.63 ; U19.9 v1(317.37,14.08) ; U4.72 243.57,14.08 ; U4.53 250.95,20.69 v1(250.71,20.45) 250.45,20.7 U4.54 ; U19.39 331.41,5.26 330.96,5.71 ; U4.60 247.45,23.75 ; U4.3 246.95,2.22 ; U19.67 331.41,23.37 ; 251.45,5.46 U4.12 251.45,2.79 v1(251.21,2.54) 250.95,2.79 U4.11 250.95,5.47 v1(251.2,5.71) 251.45,5.46 ; U4.32 258.57,13.08 v1(258.32,12.83) 258.56,12.58 U4.31 261.24,12.58 v1(261.49,12.84) 261.25,13.08 U4.32 ; 250.45,2.79 v1(250.21,2.54) 249.95,2.79 U4.9 249.95,5.47 v1(250.2,5.71) 250.45,5.46 U4.10 250.45,2.79 ; U4.33 261.24,13.58 v1(261.49,13.83) 261.25,14.08 U4.34 258.57,14.08 v1(258.32,13.83) 258.56,13.58 U4.33
  TOP w0.305: SB27.2 JP27.4 ; JP12.10 214.63,25.15 214.63,21.46 213.79,20.62 SB13.1 ; JP12.8 212.09,25.15 212.09,21.46 211.25,20.62 SB12.1 ; SB22.1 227.51,20.62 228.35,21.46 228.35,25.15 JP11.4 ; JP12.4 207.01,25.15 207.01,21.46 206.17,20.62 SB10.1 ; JP12.2 204.47,25.15 204.47,21.46 203.63,20.62 SB9.1 ; JP12.12 217.17,25.15 217.17,21.46 216.33,20.62 SB14.1 ; SB20.1 224.97,20.62 225.81,21.46 225.81,25.15 JP11.2 ; JP12.14 219.71,25.15 219.71,21.46 218.87,20.62 SB15.1 ; JP12.6 209.55,25.15 209.55,21.46 208.71,20.62 SB11.1 ; SB16.1 221.41,20.62 222.25,21.46 222.25,25.15 JP12.16
  TOP w0.381: 243.57,14.08 243.84,14.35 v1(243.84,14.73) 243.84,15.34 243.6,15.58 ; 246.95,2.22 246.95,1.65 ; 247.45,23.75 247.45,24.07 v1(247.14,24.38) ; 248.45,2.2 248.45,1.65
  TOP w0.508: 338.33,13.08 v1(338.71,12.7) 338.71,12.45 338.45,12.19 ; 331.41,23.37 331.41,23.68 v1(331.34,23.75) v1(330.33,23.75) 330.07,23.49 ; v1(369.7,6.72) U18.8 v1(374.14,6.72) ; 317.37,10.41 317.25,10.41 v1(317.12,10.29) ; v1(243.71,11.62) v1(243.71,12.51) ; v1(322.58,20.19) 323.41,20.19 323.76,20.54 ; v1(330.33,5.84) 330.83,5.84 330.96,5.71 ; v1(323.85,6.1) 324.23,5.71 324.61,5.71
  TOP w0.635: v1(243.84,26.04) 243.84,25.27 C13.2 242.82,25.27 v1(242.82,26.04) ; v1(241.94,1.02) 242.95,1.02 C12.2 243.71,1.02 v1(244.73,1.02) ; JP13.2 260.1,2.08 SB21.1 ; v1(77.34,24.26) U11.4 v1(76.46,25.91) ; v1(102.11,7.75) v1(101.22,7.75) 99.57,7.75 ; v1(101.35,25.15) C507.2 102.27,26.12 102.62,25.78 v1(102.62,25.15) ; v1(120.78,24) v1(120.78,24.89) U6.4 ; v1(100.33,15.37) 100.33,15.75 100.62,16.04 C506.2 102.07,16.04 102.36,15.75 v1(102.36,15.37) ; v1(378.46,15.88) v1(377.57,15.88) 377.57,19.31 ; 108.58,25.91 v1(108.58,27.81) ; 248.45,1.65 v1(248.45,0.89) ; U8.6 v1(51.18,27.81) ; v1(113.54,22.73) 113.54,21.72 C508.2 114.68,21.46 v1(115.19,21.97) ; U1.4 v1(20.95,3.3) ; 246.95,1.65 v1(246.95,0.89) ; U17.2 v1(393.32,11.3) ; U16.2 v1(384.18,11.3) ; v1(43.69,8.51) v1(42.8,8.51) U7.4 ; U2.4 v1(20.95,12.45) ; v1(62.99,7.75) v1(66.67,7.75) ; v1(81.66,7.75) v1(84.96,7.75) ; v1(71.25,14.61) U10.4 v1(71.25,17.91) ; U14.6 v1(90.81,27.81) ; U3.4 v1(20.95,21.59) ; U18.1 393.46,1.92 v1(392.68,1.14) v1(391.8,1.14)
  TOP w0.762: v1(35.81,4.7) C22.2 v1(34.42,6.35) ; R24.1 v1(35.05,11.68) ; R26.1 v1(35.05,9.14)
  TOP w0.889: C5.2 C27.5
  BOTTOM w0.508: C525.2 v1(240.78,19.04)
  BOTTOM w0.635: R66.1 JP20.16 ; v1(321.82,4.57) 321.69,4.45 R85.1 319.66,4.45 v1(319.53,4.57) ; C23.2 v1(28.19,18.54) ; R73.1 v1(384.18,13.97) ; C50.2 71.63,8.38 72.26,7.75 v1(72.52,7.75) ; v1(61.34,27.31) 60.12,27.31 59.78,26.96 C505.2 v1(59.78,23.71) ; R17.1 v1(11.94,1.78) ; R40.2 v1(71.63,6.1) ; R96.1 21.72,22.35 v1(20.95,21.59) ; v1(102.62,25.15) 102.62,26.42 101.95,27.08 99.85,27.08 99.4,26.63 C517.2 101.09,26.04 101.35,25.78 v1(101.35,25.15) ; R74.1 v1(387.99,13.97) ; C30.2 v1(23.11,18.54) ; R65.1 347.47,5.97 ; R28.1 v1(11.94,10.92) ; C37.2 v1(21.97,1.78) ; C40.2 v1(29.46,1.78) ; C33.2 v1(23.11,9.4) ; R93.1 21.72,4.06 v1(20.95,3.3) ; C54.2 v1(84.84,5.08) ; R69.1 347.47,21.21 ; R63.1 v1(393.32,13.97) ; 250.7,5.22 R6.2 ; 250.7,5.22 v1(251.2,5.71) ; 250.7,5.22 v1(250.2,5.71) ; R33.1 v1(11.94,20.07) ; R4.1 v1(278.89,18.54) ; R72.1 v1(397.13,13.97) ; C25.2 v1(28.19,9.4) ; R5.1 v1(276.35,18.54) ; R83.1 v1(337.69,21.72) ; R70.1 v1(337.69,19.94) ; R3.1 v1(281.43,18.54) ; R95.1 21.72,13.21 v1(20.95,12.45)
  vias: v1(31.11,21.97) v1(31.11,12.83) v1(31.11,3.68) v1(32,21.97) v1(32,12.83) v1(32,3.68) v1(32.89,21.97) v1(32.89,12.83) v1(32.89,3.68) v1(51.44,4.7) v1(51.44,3.81) v1(51.44,2.92) v1(54.99,17.14) v1(55.75,13.21) v1(55.75,12.32) v1(55.75,11.43) v1(55.75,9.4) v1(55.75,8.51) v1(55.75,7.62) v1(55.88,17.14) v1(56.52,4.7) v1(56.52,3.81) v1(56.52,2.92) v1(56.77,17.14) v1(76.58,8.13) v1(77.47,8.13) v1(78.36,8.13) v1(83.82,18.41) v1(84.71,18.41) v1(85.6,18.41) v1(94.61,17.14) v1(95.5,17.14) v1(96.39,17.14) v1(109.73,3.68) v1(110.62,3.68) v1(111.51,3.68) v1(111.63,9.78) v1(112.52,9.78) v1(113.41,9.78) v1(126.62,9.53) v1(127.13,22.1) v1(127.51,9.53) v1(128.02,22.1) v1(128.4,9.53) v1(128.91,22.1) v1(199.45,24.89) v1(200.34,24.89) v1(229.93,24.89) v1(230.82,24.89) v1(236.09,16.89) v1(236.09,16.26) v1(236.09,15.62) v1(236.09,13.84) v1(236.09,13.21) v1(236.09,12.57) v1(236.09,10.54) v1(236.09,9.91) v1(236.09,9.27) v1(248.03,18.67) v1(248.03,17.78) v1(248.03,16.89) v1(248.16,15.88) v1(248.16,14.86) v1(248.16,13.84) v1(248.16,12.32) v1(248.16,11.3) v1(248.16,10.29) v1(249.17,15.88) v1(249.17,14.86) v1(249.17,13.84) v1(249.17,12.32) v1(249.17,11.3) v1(249.17,10.29) v1(250.19,15.88) v1(250.19,14.86) v1(250.19,11.3) v1(250.19,10.29) v1(251.71,15.88) v1(251.71,14.86) v1(251.71,11.3) v1(251.71,10.29) v1(252.73,15.88) v1(252.73,14.86) v1(252.73,13.84) v1(252.73,12.32) v1(252.73,11.3) v1(252.73,10.29) v1(253.75,15.88) v1(253.75,14.86) v1(253.75,13.84) v1(253.75,12.32) v1(253.75,11.3) v1(253.75,10.29) v1(257.13,10.08) v1(265.05,14.86) v1(265.05,14.22) v1(265.05,13.59) v1(265.05,11.94) v1(265.05,11.3) v1(265.05,10.67) v1(302.26,17.14) v1(302.26,16.26) v1(302.26,15.37) v1(313.82,9.91) v1(313.82,9.02) v1(313.82,8.13) v1(325.12,15.88) v1(325.12,14.86) v1(325.12,13.84) v1(325.12,12.32) v1(325.12,11.3) v1(325.12,10.29) v1(326.14,15.88) v1(326.14,14.86) v1(326.14,13.84) v1(326.14,12.32) v1(326.14,11.3) v1(326.14,10.29) v1(327.15,15.88) v1(327.15,14.86) v1(327.15,11.3) v1(327.15,10.29) v1(328.68,15.88) v1(328.68,14.86) v1(328.68,11.3) v1(328.68,10.29) v1(329.69,15.88) v1(329.69,14.86) v1(329.69,13.84) v1(329.69,12.32) v1(329.69,11.3) v1(329.69,10.29) v1(330.71,15.88) v1(330.71,14.86) v1(330.71,13.84) v1(330.71,12.32) v1(330.71,11.3) v1(330.71,10.29) v2(250.95,13.08) v2(327.91,13.08)
0G_REF_VSRC: length 7.6
  TOP w0.635: C44.1 110.62,7.37 110.24,7.75 109.22,7.75
  TOP w1.016: JP3.9 3.81,23.37 4.95,22.23 R14.1
  vias: v1(109.73,4.95) v1(110.62,4.95) v1(111.51,4.95)
0G_VREF_P04: length 16.4
  TOP w0.254: 241.55,7.87 241.76,8.08 U4.84
  TOP w0.305: 241.55,7.87 v1(240.92,7.24) ; U4.5 247.95,2.72 247.65,2.41 v1(247.65,2.16) ; U4.2 246.45,2.74 246.32,2.61 246.32,2.1 v1(245.87,1.65)
  TOP w0.635: v1(106.68,10.29) v1(107.57,10.29) 109.22,10.29 ; v1(106.68,9.02) v1(107.57,9.02) U5.6
  BOTTOM w0.508: C523.2 244.73,6.6 245.11,6.99 v1(245.11,8) 244.86,8.26 C524.2 ; C522.2 v1(247.9,8.51)
1P8VSRC: length 3.1
  TOP w0.508: U18.7 v1(397.37,6.72) v1(398.26,6.72)
  vias: v1(321.69,12.19) v1(321.69,11.3) v1(321.69,10.41) v1(324.99,6.6) v1(325.88,6.6) v1(326.77,6.6) v1(327.66,19.56) v1(328.55,19.56) v1(329.44,19.56) v1(334.39,15.49) v1(334.39,14.61) v1(334.39,13.72) v1(374.4,2.16) v1(375.29,2.16)
3P3VSRC: length 27.8
  TOP w0.508: v1(391.41,5.92) v1(392.3,5.92) U18.6
  TOP w0.635: U15.8 v1(373.76,15.88) v1(372.87,15.88) ; U16.3 v1(385.44,11.3) ; U17.3 v1(394.59,11.3)
  BOTTOM w0.635: 319.53,17.91 v1(319.53,19.43) ; R81.2 v1(392.18,3.56) ; R81.2 R99.2 ; R81.2 R98.2 ; R64.2 v1(380.24,9.53) ; v1(391.41,5.92) v1(392.3,5.92) 392.35,5.92 392.68,5.59 R98.2 ; R98.2 v1(393.7,7.62) ; R84.1 v1(337.69,23.5) ; R67.2 v1(349.25,17.4) ; R68.2 v1(349.25,14.99)
  vias: v1(303.53,17.14) v1(303.53,16.26) v1(303.53,15.37) v1(315.09,9.91) v1(315.09,9.02) v1(315.09,8.13) v1(324.61,19.56) v1(325.5,19.56) v1(326.39,19.56) v1(331.09,6.6) v1(331.98,6.6) v1(332.23,19.18) v1(332.87,6.6) v1(332.99,19.18) v1(334.39,12.45) v1(334.39,11.56) v1(334.39,10.67) v1(368.68,4.57) v1(369.44,4.57)
5P0VSRC: length 70.4
  TOP w0.254: U4.55 249.95,20.72 249.68,20.45 249.45,20.68 U4.56 ; U4.8 249.45,5.56 249.17,5.84 248.95,5.62 U4.7 ; U4.70 240.66,15.08 240.41,14.83 240.66,14.58 U4.71 ; U4.79 240.24,10.58 240.03,10.79 240.32,11.08 U4.78
  TOP w0.635: 249.68,20.45 249.3,20.07 ; C16.1 238.35,16.26 239.78,14.83 240.41,14.83 ; U6.2 123.32,24.89 ; U5.8 110.62,11.56 111,11.94 C9.1 ; v1(94.61,10.29) v1(91.31,10.29) ; U1.7 C39.1 ; C512.1 81.15,16.26 U11.8 ; C34.1 239.14,10.79 240.03,10.79 ; 68.71,24.64 U10.7 ; 68.71,24.64 v1(69.22,24.13) ; 68.71,24.64 v1(68.2,24.13) ; U3.7 C26.1 ; C500.1 50.8,12.32 ; U2.7 C35.1 ; 74.42,10.29 77.47,10.29
  TOP w0.889: C12.1 243.33,6.1 244.21,6.98 248.55,6.98 249.17,6.35 249.17,5.84 ; C13.1 243.33,20.83 244.09,20.07 249.3,20.07 ; 123.32,24.89 123.95,24.26 C21.1
  vias: v1(31.11,23.24) v1(31.11,14.1) v1(31.11,4.95) v1(32,23.24) v1(32,14.1) v1(32,4.95) v1(32.89,23.24) v1(32.89,14.1) v1(32.89,4.95) v1(54.48,13.21) v1(54.48,12.32) v1(54.48,11.43) v1(76.58,9.4) v1(77.47,9.4) v1(78.36,9.4) v1(83.82,17.14) v1(84.71,17.14) v1(85.6,17.14) v1(111.63,11.05) v1(112.52,11.05) v1(113.41,11.05) v1(127.13,23.37) v1(128.02,23.37) v1(128.91,23.37) v1(237.36,16.89) v1(237.36,16.26) v1(237.36,15.62) v1(237.36,10.54) v1(237.36,9.91) v1(237.36,9.27) v1(242.7,22.73) v1(242.7,3.56) v1(243.33,22.73) v1(243.33,3.56) v1(243.97,22.73) v1(243.97,3.56)
8PDN_P03: length 10.5
  TOP w0.635: R503.2 94.87,24 v1(93.85,24) 90.04,24 89.53,24.51 U14.7
  BOTTOM w0.635: C517.1 95.42,25.57 v1(93.85,24)
AD_1P8VSRC: length 5.2
  TOP w0.254: U4.35 261.34,14.58 261.62,14.86 261.4,15.08 U4.36
  TOP w0.635: 261.62,14.86 262.25,14.86 C43.1
  vias: v1(263.78,14.86) v1(263.78,14.22) v1(263.78,13.59)
AD_3P3VSRC: length 74.3
  TOP w0.254: U4.28 261.33,11.08 261.62,10.79 261.41,10.58 U4.27 ; U4.30 261.35,12.08 261.62,11.81 261.39,11.58 U4.29
  TOP w0.305: SB19.1 282.12,20.37 282.7,20.95 282.7,25.15 JP10.6 ; SB17.1 277.04,20.37 277.62,20.95 277.62,25.15 JP10.2 ; JP10.4 280.16,25.15 280.16,20.95 279.58,20.37 SB18.1
  TOP w0.635: U14.3 90.81,18.16 ; 261.62,11.81 262.38,11.81 C514.1 262.38,10.79 261.62,10.79 ; 108.58,16.25 108.58,17.65 109.35,18.41 ; R503.1 C509.1 ; R500.1 C502.1 ; U8.3 51.18,18.16
  TOP w0.889: 51.18,18.16 52.32,19.3 C502.1 ; 109.35,18.41 C508.1 ; C509.1 91.95,19.3 90.81,18.16
  BOTTOM w0.635: R12.1 v1(217.2,20.42) ; R8.1 v1(204.5,20.42) ; R9.1 v1(209.58,20.42) ; R2.1 v1(223.24,20.42) ; R11.1 v1(214.66,20.42) ; 264.67,6.6 264.16,7.11 v1(264.16,7.87) ; 264.67,6.6 265.3,7.24 v1(265.3,7.87) ; 264.67,6.6 R62.2 ; R10.1 v1(212.12,20.42) ; R60.1 v1(219.74,20.42) ; R1.1 v1(207.04,20.42) ; R61.1 v1(222.28,20.42) ; R7.1 v1(225.78,20.42)
  vias: v1(54.99,18.41) v1(55.88,18.41) v1(56.77,18.41) v1(94.61,18.41) v1(95.5,18.41) v1(96.39,18.41) v1(113.54,19.56) v1(114.17,19.56) v1(199.45,23.62) v1(200.34,23.62) v1(229.93,23.62) v1(230.82,23.62) v1(263.78,11.94) v1(263.78,11.3) v1(263.78,10.67)
AD_VCOM: length 8
  TOP w0.635: JP500.1 107.19,2.08 SB7.1 ; v1(102.11,11.56) v1(101.22,11.56) U5.1 ; v1(102.11,10.29) v1(101.22,10.29) 99.57,10.29
ADC_CH1: length 251.7
  TOP w0.362: U4.4 247.45,5.39 v1(247.9,5.84)
  BOTTOM w0.362: C522.1 v1(247.9,5.84) 247.9,5.08 244.73,1.91 236.22,1.91 232.28,5.84 202.95,5.84 201.93,6.86 182.63,6.86 177.04,1.27 145.92,1.27 136.91,10.29 130.05,10.29 125.73,14.61 117.35,14.61 116.46,13.72 116.46,8.38 115.19,7.11 110.62,7.11 108.58,5.08 108.58,2.54 107.44,1.4 32,1.4 30.1,3.3 27.43,3.3 25.91,1.78 C40.1 25.15,2.92 24.13,3.94 R15.2
ADC_CH2: length 242.3
  TOP w0.362: U4.1 245.95,5.51 245.75,5.71 v1(245.11,5.71)
  BOTTOM w0.362: v1(245.11,5.71) 242.88,5.71 242.56,6.04 C523.1 242,6.6 241.74,6.35 236.22,6.35 232.41,10.16 202.56,10.16 200.15,12.57 188.85,12.57 186.63,10.35 166.18,10.35 165.23,9.4 148.97,9.4 140.84,17.53 116.71,17.53 111.12,11.94 103.25,11.94 102.62,12.57 80.9,12.57 77.72,15.75 68.58,15.75 65.28,12.45 58.29,12.45 56.26,10.41 52.2,10.41 49.4,7.62 27.34,7.62 25.15,9.81 C25.1 25.15,12.06 24.13,13.08 R31.2
ADC_CH3: length 238.6
  TOP w0.362: U4.83 240.61,8.58 v1(240.16,8.13)
  BOTTOM w0.362: C524.1 240.94,8.26 240.81,8.13 v1(240.16,8.13) 235.97,8.13 232.28,11.81 202.18,11.81 200.41,13.59 187.71,13.59 186.56,14.73 166.62,14.73 162.18,10.29 152.91,10.29 144.78,18.41 116.59,18.41 110.87,12.7 103.89,12.7 103.25,13.34 82.17,13.34 78.74,16.76 67.94,16.76 65.41,14.22 35.69,14.22 32.51,17.4 26.29,17.4 25.15,18.54 C23.1 25.15,21.21 24.13,22.23 R35.2
ADC_CH4: length 216.5
  TOP w0.362: TP8.1 239.18,4.7 v1(239.31,4.57) ; U4.80 244.53,10.08 244.57,10.03 v1(245.24,10.03) ; U9.6 v1(72.64,9.02)
  BOTTOM w0.362: C526.1 244.45,10.16 244.57,10.03 v1(245.24,10.03) 246.13,9.14 246.13,5.46 245.24,4.57 v1(239.31,4.57) 236.47,4.57 232.28,8.76 202.69,8.76 200.15,11.3 189.61,11.3 187.32,9.02 173.86,9.02 170.56,5.71 148.97,5.71 140.97,13.72 129.92,13.72 127.13,16.51 116.97,16.51 114.43,13.97 114.43,9.27 113.92,8.76 109.09,8.76 106.93,6.6 94.36,6.6 91.44,9.53 82.68,9.53 78.99,13.21 R38.2 70.61,11.43 C45.2 72.06,10.92 72.4,10.58 72.4,10.55 72.64,10.31 v1(72.64,9.02)
ADC_CH5M: length 216.1
  TOP w0.178: v1(244.88,14.73) 245.24,15.09 245.24,15.37 244.41,16.19 243.42,16.19 243.31,16.08 U4.68
  BOTTOM w0.178: 55.88,21.4 55.7,21.22 53.84,21.22 53.59,21.46 R502.1 ; 55.88,21.4 C504.1 ; 55.88,21.4 56.06,21.22 57.91,21.22 58.83,20.31 58.83,17.5 60.45,15.88 63.75,15.88 67.56,19.68 79.9,19.68 85.1,14.48 103.76,14.48 104.52,13.72 110.49,13.72 116.2,19.43 147.46,19.43 149.11,17.78 160.91,17.78 162.67,16.02 186.94,16.02 188.33,14.63 200.18,14.63 201.45,15.9 232.29,15.9 234.94,18.54 238.25,18.54 240.46,16.33 241.05,16.33 C519.2 241.81,16.33 242.24,16.33 242.7,15.88 242.7,14.37 243.19,13.87 244.99,13.87 245.24,14.11 245.24,14.37 v1(244.88,14.73)
ADC_CH5P: length 217
  TOP w0.178: v1(245.88,14.73) 245.52,15.09 245.52,15.48 244.53,16.47 243.42,16.47 243.31,16.58 U4.67
  BOTTOM w0.178: 55.88,20.76 55.7,20.94 53.84,20.94 53.59,20.7 R501.1 ; 55.88,20.76 56.06,20.94 57.8,20.94 58.55,20.19 58.55,17.38 60.34,15.6 63.87,15.6 67.68,19.41 79.78,19.41 84.99,14.2 103.64,14.2 104.41,13.44 110.61,13.44 116.32,19.15 147.35,19.15 149,17.5 160.79,17.5 162.55,15.74 186.82,15.74 188.21,14.35 200.29,14.35 201.56,15.62 232.41,15.62 235.05,18.26 238.14,18.26 240.35,16.05 241.05,16.05 C519.1 241.81,16.05 242.12,16.05 242.42,15.76 242.42,14.25 243.08,13.59 245.11,13.59 245.52,14 245.52,14.37 v1(245.88,14.73) ; 55.88,20.76 C504.2
ADC_CH6: length 210.3
  TOP w0.362: v1(238.38,24.38) 238.38,23.38 238.12,23.11 TP10.1 ; U4.64 242,18.87 v1(241.82,19.05)
  BOTTOM w0.362: C54.1 89.15,6.6 R45.2 90.93,7.11 92.58,5.46 107.19,5.46 109.66,7.94 114.49,7.94 115.44,8.89 115.44,13.84 117.35,15.75 126.24,15.75 129.92,12.06 138.81,12.06 148.84,2.03 175.77,2.03 181.61,7.87 187.71,7.87 190.25,10.41 199.77,10.41 202.82,7.37 232.16,7.37 236.85,2.67 244.35,2.67 246.89,5.21 246.89,15.11 246,16 243.59,16 242.7,16.89 242.7,17.27 241.82,18.15 C525.1 v1(241.82,19.05) 241.82,20.18 238.38,23.62 v1(238.38,24.38)
ADC_CH7M: length 173.6
  TOP w0.178: TP12.1 255.46,26.16 255.64,25.98 255.64,24.39 255.26,24 250.06,24 249.83,24.23 249.83,26.01 248.92,26.92 246.13,26.92 245.8,26.6 245.8,25.98 v1(245.47,25.65) 245.8,25.32 245.8,24.4 246.56,23.63 246.56,23.46 246.45,23.35 U4.62
  BOTTOM w0.178: 112.01,21.4 111.84,21.22 109.98,21.22 ; 112.01,21.4 C57.1 ; 112.01,21.4 112.19,21.22 152.41,21.22 153.67,22.48 161.67,22.48 165.1,19.05 186.69,19.05 189.2,16.54 199.4,16.54 201.15,18.29 231,18.29 233.4,20.69 233.4,23.48 236.84,26.92 240.17,26.92 242.56,24.54 243.34,24.54 C520.2 244.11,24.51 245.1,24.51 245.8,25.22 245.8,25.32 v1(245.47,25.65) ; 109.98,21.22 R49.1 ; 109.98,21.22 108.33,21.22 107.95,21.6 R47.1
ADC_CH7P: length 174.1
  TOP w0.178: TP11.1 256.1,26.16 255.92,25.98 255.92,24.27 255.37,23.72 249.95,23.72 249.56,24.12 249.56,25.89 248.8,26.64 246.24,26.64 246.08,26.48 246.08,25.98 v1(246.41,25.65) 246.08,25.32 246.08,24.51 246.84,23.75 246.84,23.46 246.95,23.35 U4.61
  BOTTOM w0.178: R50.1 109.98,20.94 ; 109.98,20.94 111.84,20.94 112.01,20.76 ; 109.98,20.94 108.32,20.94 107.95,20.57 R51.1 ; 112.01,20.76 C57.2 ; 112.01,20.76 112.19,20.94 152.53,20.94 153.79,22.2 161.56,22.2 164.98,18.77 186.57,18.77 189.09,16.26 199.52,16.26 201.27,18.01 231.11,18.01 233.68,20.57 233.68,23.37 236.96,26.64 240.06,26.64 242.44,24.26 243.32,24.26 C520.1 244.08,24.23 245.21,24.23 246.08,25.1 246.08,25.32 v1(246.41,25.65)
ADC_CH8M: length 187.6
  TOP w0.178: U4.59 247.95,23.35 248.06,23.46 248.06,25.3 v1(247.73,25.63)
  BOTTOM w0.178: 92.2,21.22 94.06,21.22 94.23,21.4 ; 92.2,21.22 90.55,21.22 90.17,21.6 R54.1 ; 92.2,21.22 R57.1 ; 94.23,21.4 94.41,21.22 96.39,21.22 97.05,20.56 97.05,19.15 98.4,17.81 102.1,17.81 105.27,14.63 110.13,14.63 115.82,20.32 150.37,20.32 152.02,18.67 162.57,18.67 163.31,17.93 186.55,17.93 188.84,15.65 199.8,15.65 201.07,16.92 231.15,16.92 234.67,20.44 234.67,22.85 237.6,25.78 238.65,25.78 242.97,21.46 249.92,21.46 250.3,21.85 250.3,22.48 C521.2 250.3,23.24 250.3,23.84 249.76,24.38 248.54,24.38 248.06,24.86 248.06,25.3 v1(247.73,25.63) ; 94.23,21.4 C511.1
ADC_CH8P: length 188
  TOP w0.178: v1(248.67,25.63) 248.34,25.3 248.34,23.46 248.45,23.35 U4.58
  BOTTOM w0.178: 92.2,20.94 90.54,20.94 90.17,20.57 R56.1 ; 92.2,20.94 94.06,20.94 94.23,20.76 ; 92.2,20.94 R58.1 ; 94.23,20.76 94.41,20.94 96.28,20.94 96.77,20.45 96.77,19.04 98.28,17.53 101.98,17.53 105.16,14.35 110.25,14.35 115.94,20.04 150.25,20.04 151.9,18.39 162.46,18.39 163.19,17.65 186.44,17.65 188.72,15.37 199.91,15.37 201.18,16.64 231.27,16.64 234.95,20.32 234.95,22.73 237.72,25.5 238.53,25.5 242.85,21.18 250.04,21.18 250.58,21.73 250.58,22.48 C521.1 250.58,23.24 250.58,23.95 249.87,24.66 248.65,24.66 248.34,24.98 248.34,25.3 v1(248.67,25.63) ; 94.23,20.76 C511.2
ADC_EVENT_P05: length 62.1
  TOP w0.254: v1(338.96,16.08) U19.59
  TOP w0.305: 382.9,19.31 v1(382.9,17.4)
  L4_SIG w0.305: v1(382.9,17.4) 381.76,18.54 367.41,18.54 358.39,27.56 343.92,27.56 341.76,25.4 341.76,24.38 339.6,22.23 339.6,16.72 v1(338.96,16.08)
  BOTTOM w0.305: v1(382.9,17.4) R73.2
ADCLK: length 44.6
  TOP w0.254: v1(258.19,15.37) 258.4,15.58 U4.37
  TOP w0.305: SB36.2 JP16.11
  L5_SIG w0.305: v1(258.19,15.37) 258.83,15.37 259.08,15.11 262.51,15.11 263.02,15.62 271.27,15.62 272.42,14.48 290.32,14.48 291.08,13.72 291.08,9.33 JP16.11
